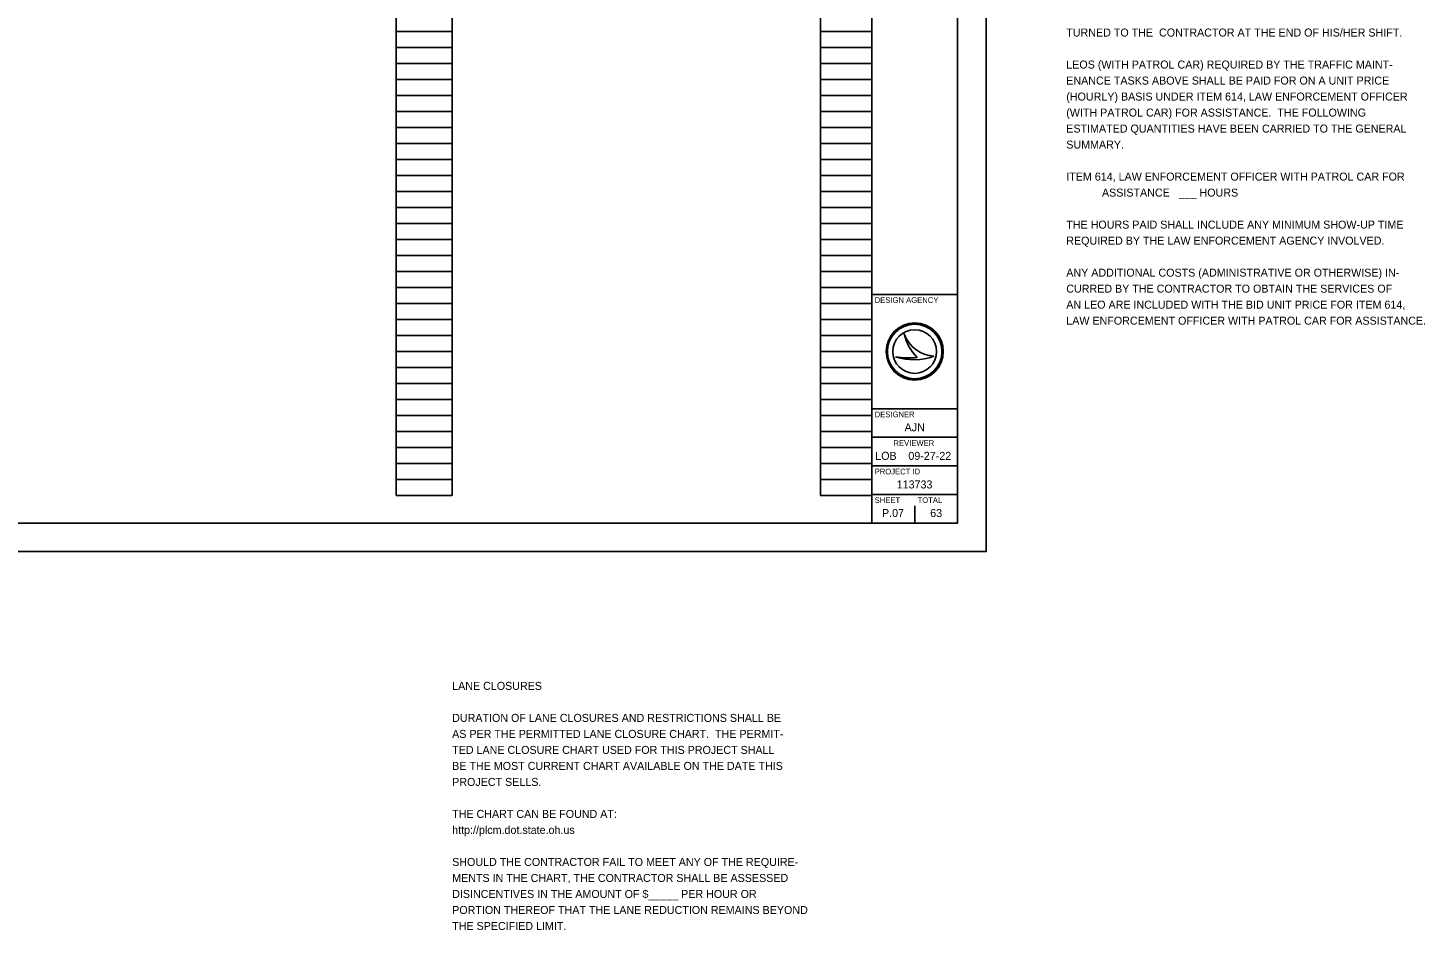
# Model space of a CAD drawing. Extents: x -7.4 to 41.7, y -6.6 to 28.2.
# Drawn here: x 17.24 to 41.68, y -6.62 to 9.16 of the extents above; entities that cross this region are included whole.
import ezdxf

# ---------------------------------------------------------------- set-up
doc = ezdxf.new("R2010")
doc.units = 0
for name, color, linetype in [('SH_Border', 7, 'Continuous'), ('SH_Cut_Line', 7, 'Continuous'), ('SH_Data', 7, 'Continuous'), ('SH_Text', 7, 'Continuous')]:
    doc.layers.add(name, color=color, linetype=linetype)

msp = doc.modelspace()

# ---------------------------------------------------------------- linework, layer by layer
at = {"layer": 'SH_Border'}
for p, q in [((32, 0.5), (32, 21.5)), ((32, 4.5), (33.5, 4.5)), ((32, 2.5), (33.5, 2.5)), ((32, 2), (33.5, 2)), ((32, 1.5), (33.5, 1.5)), ((32, 1), (33.5, 1))]:
    msp.add_line(p, q, dxfattribs=at)
msp.add_lwpolyline([(1.5, 21.5), (33.5, 21.5), (33.5, 0.5), (1.5, 0.5)], close=True, dxfattribs=at)
at = {"layer": 'SH_Cut_Line'}
msp.add_lwpolyline([(0, 0), (34, 0), (34, 22), (0, 22)], close=True, dxfattribs=at)
at = {"layer": 'SH_Data'}
for p, q in [((23.68, 0.98), (23.68, 21.14)), ((24.66, 0.98), (24.66, 21.14)), ((31.1, 0.98), (31.1, 21.14)), ((32, 0.98), (32, 21.14)), ((23.68, 9.1), (24.66, 9.1)), ((31.1, 9.1), (32, 9.1)), ((23.68, 8.82), (24.66, 8.82)), ((31.1, 8.82), (32, 8.82)), ((23.68, 8.54), (24.66, 8.54)), ((31.1, 8.54), (32, 8.54)), ((23.68, 8.26), (24.66, 8.26)), ((31.1, 8.26), (32, 8.26)), ((23.68, 7.98), (24.66, 7.98)), ((31.1, 7.98), (32, 7.98)), ((23.68, 7.7), (24.66, 7.7)), ((31.1, 7.7), (32, 7.7)), ((23.68, 7.42), (24.66, 7.42)), ((31.1, 7.42), (32, 7.42)), ((23.68, 7.14), (24.66, 7.14)), ((31.1, 7.14), (32, 7.14)), ((23.68, 6.86), (24.66, 6.86)), ((31.1, 6.86), (32, 6.86)), ((23.68, 6.58), (24.66, 6.58)), ((31.1, 6.58), (32, 6.58)), ((23.68, 6.3), (24.66, 6.3)), ((31.1, 6.3), (32, 6.3)), ((23.68, 6.02), (24.66, 6.02)), ((31.1, 6.02), (32, 6.02)), ((23.68, 5.74), (24.66, 5.74)), ((31.1, 5.74), (32, 5.74)), ((23.68, 5.46), (24.66, 5.46)), ((31.1, 5.46), (32, 5.46)), ((23.68, 5.18), (24.66, 5.18)), ((31.1, 5.18), (32, 5.18)), ((23.68, 4.9), (24.66, 4.9)), ((31.1, 4.9), (32, 4.9)), ((23.68, 4.62), (24.66, 4.62)), ((31.1, 4.62), (32, 4.62)), ((23.68, 4.34), (24.66, 4.34)), ((31.1, 4.34), (32, 4.34)), ((23.68, 4.06), (24.66, 4.06)), ((31.1, 4.06), (32, 4.06)), ((23.68, 3.78), (24.66, 3.78)), ((31.1, 3.78), (32, 3.78)), ((32.567, 3.81), (32.567, 3.81)), ((23.68, 3.5), (24.66, 3.5)), ((31.1, 3.5), (32, 3.5)), ((32.75, 3.5), (32.75, 3.5)), ((23.68, 3.22), (24.66, 3.22)), ((31.1, 3.22), (32, 3.22)), ((32.417, 3.41), (32.417, 3.41)), ((33.087, 3.419), (33.087, 3.419)), ((23.68, 2.94), (24.66, 2.94)), ((31.1, 2.94), (32, 2.94)), ((23.68, 2.66), (24.66, 2.66)), ((31.1, 2.66), (32, 2.66)), ((23.68, 2.38), (24.66, 2.38)), ((31.1, 2.38), (32, 2.38)), ((23.68, 2.1), (24.66, 2.1)), ((31.1, 2.1), (32, 2.1)), ((23.68, 1.82), (24.66, 1.82)), ((31.1, 1.82), (32, 1.82)), ((23.68, 1.54), (24.66, 1.54)), ((31.1, 1.54), (32, 1.54)), ((23.68, 1.26), (24.66, 1.26)), ((31.1, 1.26), (32, 1.26)), ((23.68, 0.98), (24.66, 0.98)), ((31.1, 0.98), (32, 0.98)), ((32.75, 0.5), (32.75, 0.8)), ((32.375, 0.675), (32.375, 0.675))]:
    msp.add_line(p, q, dxfattribs=at)
for radius in [0.5, 0.477, 0.477, 0.382]:
    msp.add_circle((32.75, 3.5), radius, dxfattribs=at)
for centre, radius, start, end in [((33.116, 3.998), 0.58, 198.9257, 198.9319), ((33.347, 3.97), 0.796, 191.6379, 191.6421), ((33.116, 3.998), 0.58, 198.9319, 267.1657), ((33.347, 3.97), 0.796, 191.6421, 226.0947), ((32.739, 4.37), 1.013, 251.4576, 290.0832), ((32.648, 4.654), 1.266, 259.4964, 259.4995), ((32.739, 4.37), 1.013, 251.4527, 251.4576), ((32.648, 4.654), 1.266, 259.4995, 276.6672)]:
    msp.add_arc(centre, radius, start, end, dxfattribs=at)

# ---------------------------------------------------------------- texts
for s, height, p in [('DESIGN AGENCY', 0.1, (32.05, 4.35)), ('DESIGNER', 0.1, (32.05, 2.35)), ('AJN', 0.14, (32.573, 2.105)), ('LOB', 0.14, (32.06, 1.605)), ('REVIEWER', 0.1, (32.378, 1.85)), ('09-27-22', 0.14, (32.639, 1.605)), ('PROJECT ID', 0.1, (32.05, 1.35)), ('113733', 0.14, (32.435, 1.105)), ('SHEET', 0.1, (32.05, 0.85)), ('P.07', 0.14, (32.178, 0.605)), ('TOTAL', 0.1, (32.8, 0.85)), ('63', 0.14, (33.021, 0.605))]:
    msp.add_text(s, height=height, dxfattribs=at).set_placement(p)
at = {"layer": 'SH_Text'}
for s, p in [('TURNED TO THE  CONTRACTOR AT THE END OF HIS/HER SHIFT.', (35.401, 9.01)), ('LEOS (WITH PATROL CAR) REQUIRED BY THE TRAFFIC MAINT-', (35.401, 8.45)), ('ENANCE TASKS ABOVE SHALL BE PAID FOR ON A UNIT PRICE', (35.401, 8.17)), ('(HOURLY) BASIS UNDER ITEM 614, LAW ENFORCEMENT OFFICER', (35.401, 7.89)), ('(WITH PATROL CAR) FOR ASSISTANCE.  THE FOLLOWING', (35.401, 7.61)), ('ESTIMATED QUANTITIES HAVE BEEN CARRIED TO THE GENERAL', (35.401, 7.33)), ('SUMMARY.', (35.401, 7.05)), ('ITEM 614, LAW ENFORCEMENT OFFICER WITH PATROL CAR FOR', (35.401, 6.49)), ('            ASSISTANCE   ___ HOURS', (35.401, 6.21)), ('THE HOURS PAID SHALL INCLUDE ANY MINIMUM SHOW-UP TIME', (35.401, 5.65)), ('REQUIRED BY THE LAW ENFORCEMENT AGENCY INVOLVED.', (35.401, 5.37)), ('ANY ADDITIONAL COSTS (ADMINISTRATIVE OR OTHERWISE) IN-', (35.401, 4.81)), ('CURRED BY THE CONTRACTOR TO OBTAIN THE SERVICES OF', (35.401, 4.53)), ('AN LEO ARE INCLUDED WITH THE BID UNIT PRICE FOR ITEM 614,', (35.401, 4.25)), ('LAW ENFORCEMENT OFFICER WITH PATROL CAR FOR ASSISTANCE.', (35.401, 3.97)), ('LANE CLOSURES', (24.66, -2.419)), ('DURATION OF LANE CLOSURES AND RESTRICTIONS SHALL BE', (24.66, -2.979)), ('AS PER THE PERMITTED LANE CLOSURE CHART.  THE PERMIT-', (24.66, -3.259)), ('TED LANE CLOSURE CHART USED FOR THIS PROJECT SHALL', (24.66, -3.539)), ('BE THE MOST CURRENT CHART AVAILABLE ON THE DATE THIS', (24.66, -3.819)), ('PROJECT SELLS.', (24.66, -4.099)), ('THE CHART CAN BE FOUND AT:', (24.66, -4.659)), ('http://plcm.dot.state.oh.us', (24.66, -4.939)), ('SHOULD THE CONTRACTOR FAIL TO MEET ANY OF THE REQUIRE-', (24.66, -5.499)), ('MENTS IN THE CHART, THE CONTRACTOR SHALL BE ASSESSED', (24.66, -5.779)), ('DISINCENTIVES IN THE AMOUNT OF $_____ PER HOUR OR', (24.66, -6.059)), ('PORTION THEREOF THAT THE LANE REDUCTION REMAINS BEYOND', (24.66, -6.339)), ('THE SPECIFIED LIMIT.', (24.66, -6.619))]:
    msp.add_text(s, height=0.14, dxfattribs=at).set_placement(p)

doc.saveas('drawing.dxf')
